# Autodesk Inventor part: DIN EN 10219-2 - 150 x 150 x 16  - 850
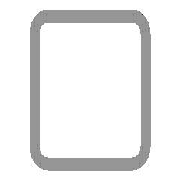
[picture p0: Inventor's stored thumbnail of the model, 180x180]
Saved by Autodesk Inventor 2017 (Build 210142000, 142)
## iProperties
IsCustomPart: 1
Created: 2016-02
Part Number: DIN EN 10219-2 - 150 x 150 x 16  - 850
Material: Steel, Mild
Description: Cold formed welded structural hollow sections of non-alloy and fine grain structural steel
Document SubType Name: Modeling
Standard: DIN
Designer: iusti
Standard Revision: 2006-07
Standards Organization: DIN
Language: en-US
Size Designation: 150 x 150 x 16
Categories: <MemberInstance><Categories><Category DisplayName="Structural Shapes" InternalName="089c4875-fa83-4c05-b084-43b9cc11f5ed" Mnemonic="GRDR"><CategoryParameter Dis
Stock Number: 150 x 150 x 16
Mass: 49891.9 g
Surface Area: 8094.11 cm^2
Volume: 6355.65 cm^3
Density: 7.85 g/cm^3
Appearance: Semi-Polished
_CCFamilyMember: 76
_CCFamilyDisplayName: DIN EN 10219-2 (Square Hollow Section - Cold Formed) - Cold formed welded structural hollow sections of non-alloy and fine grain structural steel
_FrameMemberDoc: Frame Member File
_Version: 15.0.0
_GetPNFromCC: 1
G_L: 850.000 mm
G_W: 150.000 mm
G_H: 150.000 mm
+25E8C026-FEE3-4A01-9593-771C732A64D6+CUTDETAIL1: Cut
+634D56CB-A472-4F3D-9CA9-6F5BA560080E+CUTDETAIL2: Cut
Author: iusti
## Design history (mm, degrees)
node "Start plane"
node "End plane"
sketch "Sketch"
  geometry: L1 (-75, -27)-(-75, 27); L2 (-27, 75)-(27, 75); L3 (75, 27)-(75, -27); L4 (27, -75)-(-27, -75); L5 (-27, 59)-(27, 59); L6 (59, 27)-(59, -27); L7 (27, -59)-(-27, -59); L8 (-59, -27)-(-59, 27); L9 (0, 118.918)-(0, -118.918) reference; L10 (-118.918, 0)-(118.918, 0) reference; A1 r 48 centre (-27, -27) between (-75, -27) and (-27, -75); A2 r 48 centre (-27, 27) between (-27, 75) and (-75, 27); A3 r 48 centre (27, 27) between (75, 27) and (27, 75); A4 r 48 centre (27, -27) between (27, -75) and (75, -27); A5 r 32 centre (-27, 27) between (-27, 59) and (-59, 27); A6 r 32 centre (27, 27) between (59, 27) and (27, 59); A7 r 32 centre (27, -27) between (27, -59) and (59, -27); A8 r 32 centre (-27, -27) between (-59, -27) and (-27, -59)
  constraints: 16 end point, 16 point on circle, 8 centre point, 8 tangent, 4 parallel, 3 equal radius, 2 perpendicular, 7 other
  dimensions: "d7" = 48 radius of A1 (= G_IR); "d10" = 150 distance between parallel lines of L2 L4 (= G_H); "d11" = 150 distance between parallel lines of L1 L3 (= G_W); "d12" = 16 distance between parallel lines of L3 L6 (= G_T); "d15" = 75 distance between parallel lines of L2 L10 (= 0.5 x d10); "d16" = 75 distance between parallel lines of L9 L3 (= 0.5 x d11)
extrude "Body" new body sketch "Sketch" stored distance "d3" = 850 (= G_L); taper "d4" = 0 deg
node "Driven Length"
  sketch "Sketch3"
    geometry: L1 (0, 0)-(10, 0) reference
    constraints: 2 end point, 1 horizontal
  workplane "Work Plane3"
  sketch "Sketch4"
    geometry: L1 (-2, 75)-(12, 75) reference; L2 (-2, 925)-(12, 925) reference
    dimensions: "d18" = 850 distance between parallel lines of L1 L2 (derived)
workplane "Work Plane4"
split "Split1"
workplane "Work Plane5"
split "Split2"
body "Solid1"
other parameters: "G_W" = 150 [user parameter; used in 1 equation term], "G_H" = 150 [user parameter; used in 1 equation term], "G_T" = 16 [user parameter; used in 1 equation term], "G_IR" = 48 [user parameter; used in 1 equation term], "G_L" = 850 (= d18) [user parameter; used in 1 equation term], "G_OFFSET_START" = -75 [user parameter; used in 1 equation term], "G_OFFSET_END" = -75 [user parameter; used in 1 equation term], "d13" = 75 (= -G_OFFSET_START), "d14" = 925 (= G_OFFSET_END + B_L), "d17" = 90 deg
